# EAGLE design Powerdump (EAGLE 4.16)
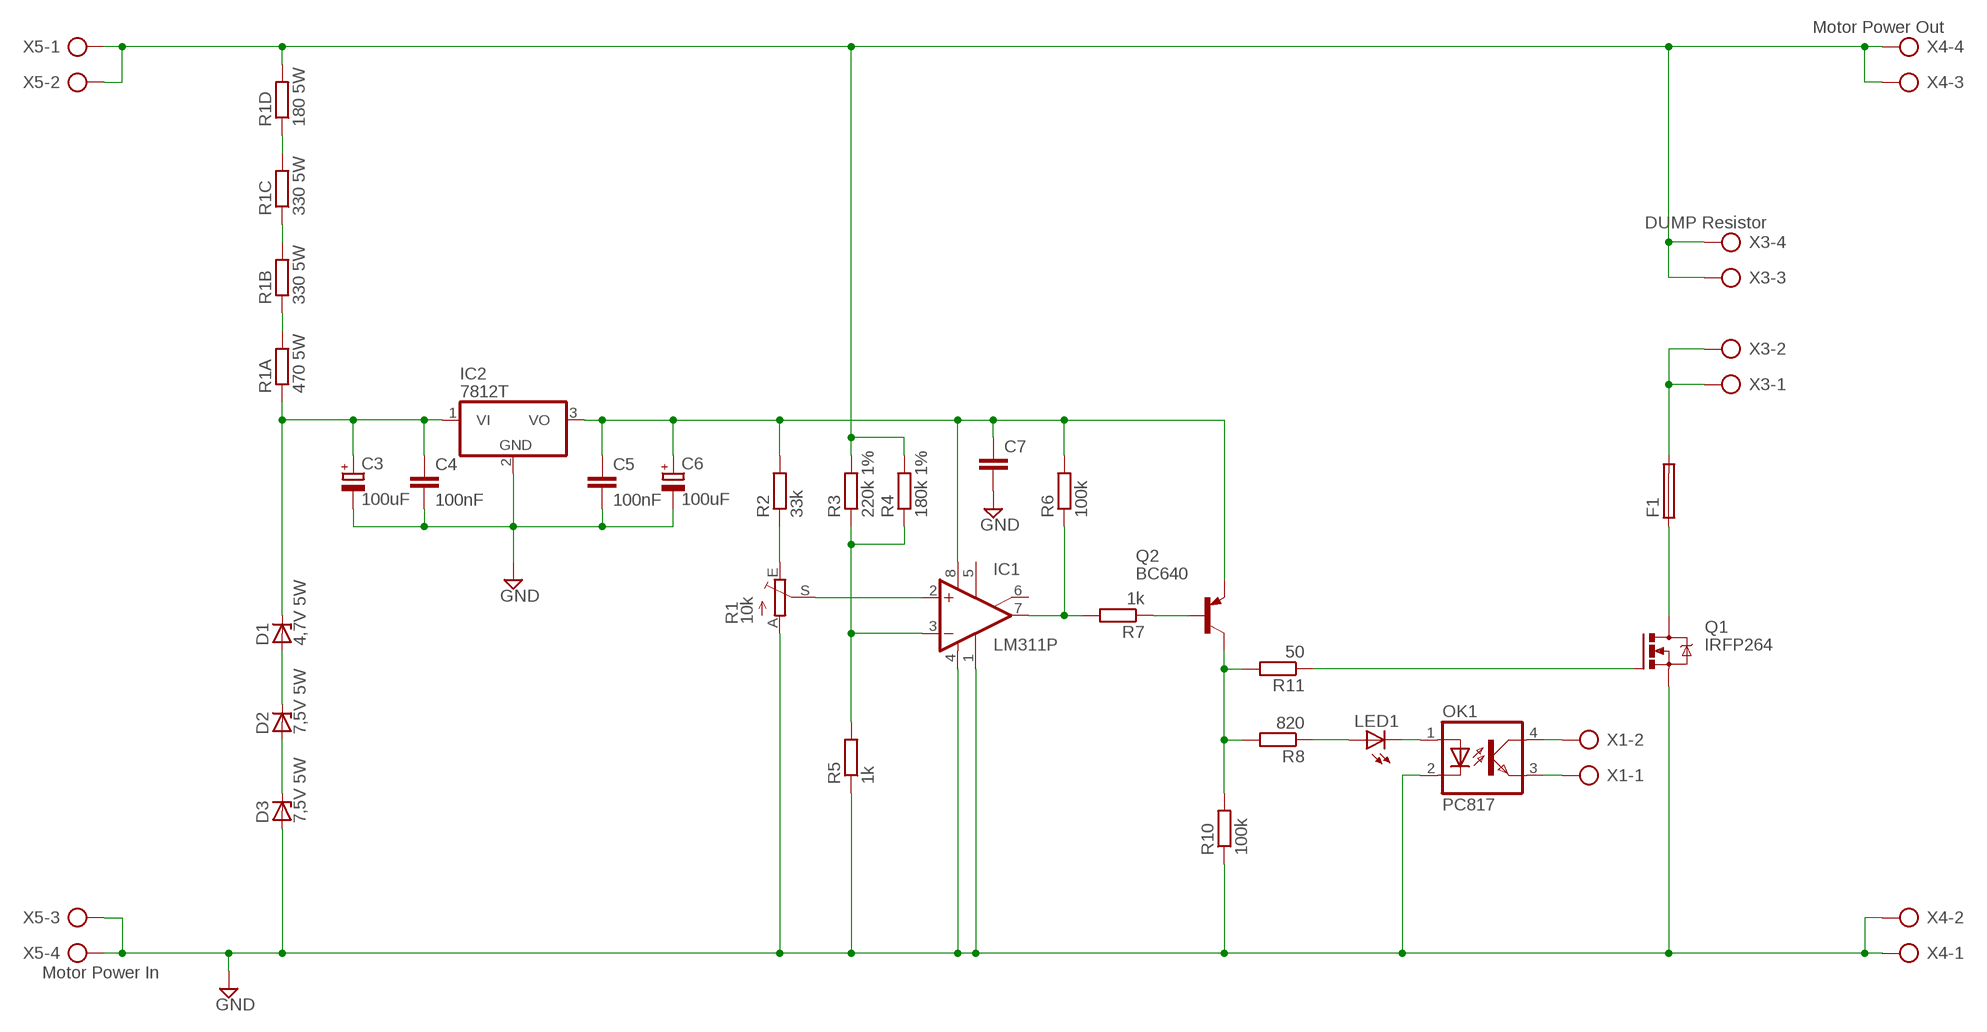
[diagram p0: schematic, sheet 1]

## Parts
C3  100uF  CPOL-EUE3.5-10  [E3,5-10]
C4  100nF  C-EU075-032X103  [C075-032X103]
C5  100nF  C-EU075-032X103  [C075-032X103]
C6  100uF  CPOL-EUE3.5-10  [E3,5-10]
C7  C-EU075-032X103  [C075-032X103]
D1  4,7V 5W  ZENER-DIODEC1702-15  [C1702-15]
D2  7,5V 5W  ZENER-DIODEC1702-15  [C1702-15]
D3  7,5V 5W  ZENER-DIODEC1702-15  [C1702-15]
F1  SH22,5A  [SH22,5A]
IC1  LM311P  LM311N  [DIL08]
IC2  7812T  [TO220H]
LED1  LED5MM  [LED5MM]
OK1  PC817  [DIL04]
Q1  IRFP264  IRFPC40  [TO247BV]
Q2  BC640  [TO92-BCE]
R1  10k  TRIM_EU-S64W  [S64W]
R1A  470 5W  R-EU_0922/22  [0922/22]
R1B  330 5W  R-EU_0922/22  [0922/22]
R1C  330 5W  R-EU_0922/22  [0922/22]
R1D  180 5W  R-EU_0922/22  [0922/22]
R2  33k  R-EU_0207/12  [0207/12]
R3  220k 1%  R-EU_0207/12  [0207/12]
R4  180k 1%  R-EU_0207/12  [0207/12]
R5  1k  R-EU_0207/12  [0207/12]
R6  100k  R-EU_0207/12  [0207/12]
R7  1k  R-EU_0207/12  [0207/12]
R8  820  R-EU_0207/12  [0207/12]
R10  100k  R-EU_0207/12  [0207/12]
R11  50  R-EU_0207/12  [0207/12]
X1  AK300/2  [AK300/2]
X3  DUMP Resistor  AK500/4  [AK500/4]
X4  Motor Power Out  AK500/4  [AK500/4]
X5  Motor Power In  AK500/4  [AK500/4]

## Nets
GND: C3.- C4.2 C5.2 C6.- C7.2 D3.A IC1.1(GND) IC1.4(V-) IC2.2(GND) OK1.2(C) Q1.S R1.A R5.1 R10.1 X4.1 X4.2 X5.3 X5.4
N$1: R1C.2 R1D.1
N$2: R1B.2 R1C.1
N$3: R1A.2 R1B.1
N$4: C3.+ C4.1 D1.C IC2.1(VI) R1A.1
N$6: C5.1 C6.+ C7.1 IC1.8(V+) IC2.3(VO) Q2.E R2.2 R6.2
N$7: IC1.7(OUT) R6.1 R7.2
N$8: Q2.B R7.1
N$11: IC1.3(-IN) R3.1 R4.1 R5.2
N$12: IC1.2(+IN) R1.S
N$13: R1.E R2.1
N$14: Q1.G R11.1
N$15: LED1.K(C) OK1.1(A)
N$16: LED1.A R8.1
N$17: Q2.C R8.2 R10.2 R11.2
N$18: R1D.2 R3.2 R4.2 X3.3 X3.4 X4.3 X4.4 X5.1 X5.2
N$19: F1.1 Q1.D
N$20: F1.2 X3.1 X3.2
N$21: D1.A D2.C
N$22: D2.A D3.C
N$24: OK1.3(EMIT) X1.1
N$25: OK1.4(COL) X1.2
Unconnected: IC1.5(ON) IC1.6(ON/STR)

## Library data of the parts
C3 C6 = rcl:CPOL-EU: POLARIZED CAPACITOR, European symbol
C4 C5 C7 = rcl:C-EU: CAPACITOR, European symbol
D1-D3 = diode:ZENER-DIODE: Z-Diode
F1 = fuse:SH22,5A: FUSE HOLDER
IC1 = linear:LM311: COMPARATOR
IC2 = linear:78*: Positive VOLTAGE REGULATOR Source: http://cache.national.com/ds/LM/LM78L05.pdf http://www.fairchildsemi.com/ds/LM/LM7805.pdf
LED1 = led:LED: LED
OK1 = optocoupler:PC817: SHARP OPTO COUPLER
Q1 = transistor-power:IRFPC40: N-CHANNEL MOS FET
Q2 = transistor-pnp:BC640*: PNP Transistror
R1 = pot:TRIM_EU-: POTENTIOMETER
R1A R1B R1C R1D R2-R8 R10 R11 = rcl:R-EU_: RESISTOR, European symbol
X1 = con-ptr500:AK300/2: CONNECTOR
X3-X5 = con-ptr500:AK500/4: CONNECTOR

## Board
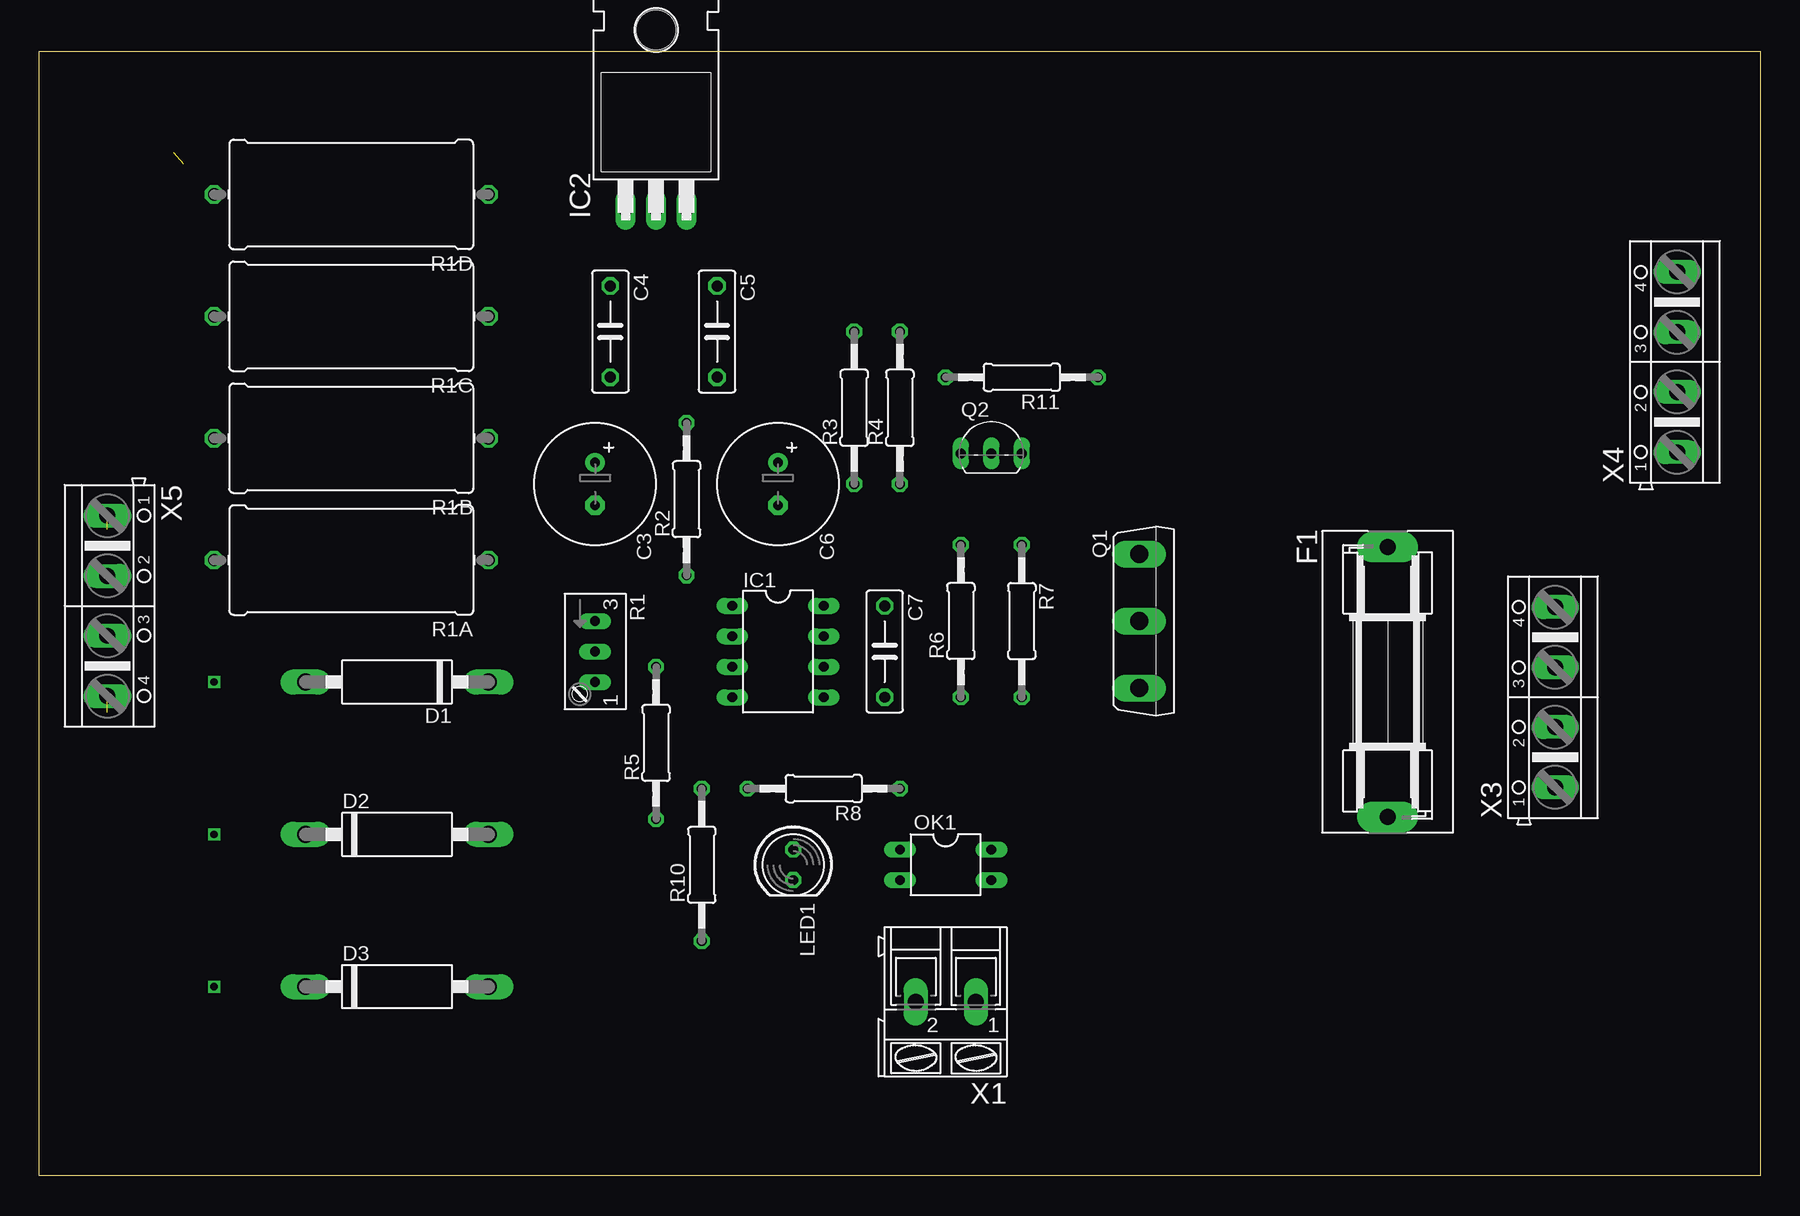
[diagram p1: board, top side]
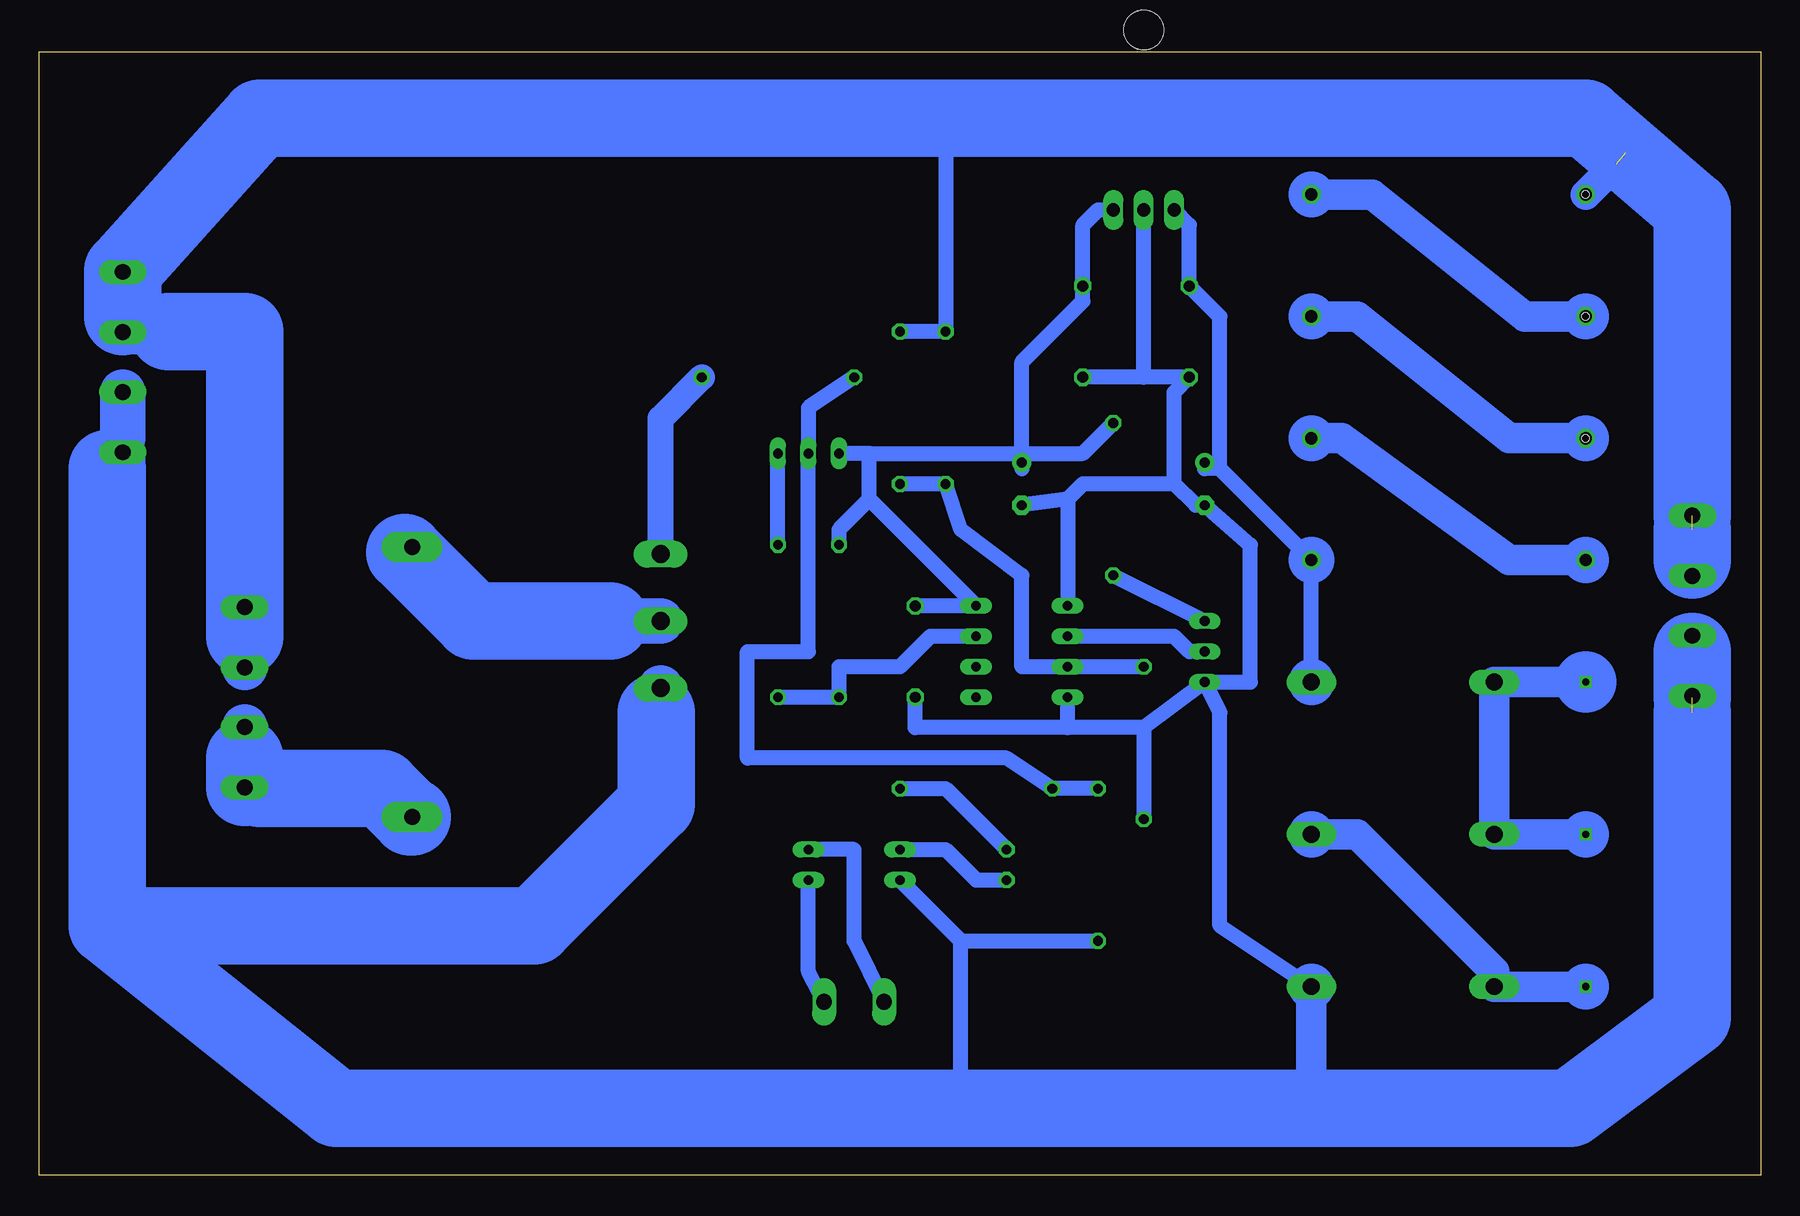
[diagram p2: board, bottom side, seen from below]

Size 143.49 x 93.65 mm. Coordinates in mm from the lower left corner, seen from the top.
Outline: 0,0 143.49,0 143.49,93.65 0,93.65 0,0
Copper layers (1*16): Top 0.035mm / dielectric 1.5mm / Bottom 0.035mm
Design rules "default": minimum track width 10mil, minimum drill 24mil, track to track 8mil, track to pad 8mil, pad to pad 8mil, via to via 8mil, smd to smd 8mil, copper to edge 40mil, drill to drill 8mil, minimum pad ring 10mil, minimum via ring 8mil, stop-mask expansion 4mil, vias tented up to drill 0mil, thermal gap 10mil
Holes 0.6 mm at 14.6,81.75 14.6,71.59 14.6,61.43

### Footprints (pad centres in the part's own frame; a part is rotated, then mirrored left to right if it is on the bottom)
E3,5-10 = drill 0.813 pad 1.6 round: + -1.778,0 | drill 0.813 pad 1.6 octagon: - 1.778,0
C075-032X103 = drill 0.914 octagon: 1 -3.81,0; 2 3.81,0
C1702-15 = drill 1.397 long: A 7.62,0; C -7.62,0
SH22,5A = drill 1.321 pad 2.54 long: 1 -11.252,0; 2 11.252,0
DIL08 = drill 0.813 long: 1 -3.81,-3.81; 2 -1.27,-3.81; 3 1.27,-3.81; 4 3.81,-3.81; 5 3.81,3.81; 6 1.27,3.81; 7 -1.27,3.81; 8 -3.81,3.81
TO220H = drill 1.118 long: 1 -2.54,-10.16; 2 0,-10.16; 3 2.54,-10.16 | hole 3.302: 0,4.826
LED5MM = drill 0.813 octagon: A -1.27,0; K 1.27,0
DIL04 = drill 0.813 long: 1 -1.27,-3.81; 2 1.27,-3.81; 3 1.27,3.81; 4 -1.27,3.81
TO247BV = drill 1.499 long: D 0,-2.921; G -5.588,-2.921; S 5.588,-2.921
TO92-BCE = drill 0.813 long: B 2.54,0; C 0,0; E -2.54,0
S64W = drill 0.813 long: A 2.54,1.27; E -2.54,1.27; S 0,1.27
0922/22 = drill 1.016 octagon: 1 -11.43,0; 2 11.43,0
0207/12 = drill 0.813 octagon: 1 -6.35,0; 2 6.35,0
AK300/2 = drill 1.321 long: 1 -2.515,0; 2 2.489,0
AK500/4 = drill 1.321 long: 1 -7.518,0; 2 -2.489,0; 3 2.489,0; 4 7.518,0

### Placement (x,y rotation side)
C3  46.35,57.62 270 top
C4  47.62,70.32 270 top
C5  56.51,70.32 270 top
C6  61.59,57.62 270 top
C7  70.48,43.65 270 top
D1  29.84,41.11 180 top
D2  29.84,28.41 0 top
D3  29.84,15.71 0 top
F1  112.39,41.11 270 top
IC1  61.59,43.65 270 top
IC2  51.43,90.64 0 top
LED1  62.86,25.87 270 top
OK1  75.56,25.87 270 top
Q1  94.61,46.19 270 top
Q2  79.37,60.16 0 top
R1  45.08,43.65 270 top
R1A  26.03,51.27 180 top
R1B  26.03,61.43 180 top
R1C  26.03,71.59 180 top
R1D  26.03,81.75 180 top
R2  53.97,56.35 90 top
R3  67.94,63.97 90 top
R4  71.75,63.97 90 top
R5  51.43,36.03 90 top
R6  76.83,46.19 90 top
R7  81.91,46.19 270 top
R8  65.4,32.22 180 top
R10  55.24,25.87 90 top
R11  81.91,66.51 180 top
X1  75.56,14.44 180 top
X3  126.36,39.84 90 top
X4  136.52,67.78 90 top
X5  5.71,47.46 270 top

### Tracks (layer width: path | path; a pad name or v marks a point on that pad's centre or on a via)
GND  (1 unrouted)
  Bottom 0.254: 5.71,43.65 X5.3 | X4.1 136.52,61.43
  Bottom 1.27: 48.89,57.62 47.11,55.84 C3.- 42.54,52.54 42.54,41.11 R1.A | 48.89,57.62 48.89,65.24 C4.2 51.43,66.51 | 51.43,66.51 C5.2 | 51.43,66.51 IC2.2 | 48.89,57.62 56.51,57.62 57.78,56.35 | 57.78,56.35 C6.- | R1.A 51.43,37.3 | 51.43,37.3 57.78,37.3 | 57.78,37.3 70.48,37.3 C7.2 | 57.78,37.3 IC1.4 | R1.A 45.08,38.57 45.08,20.79 D3.A | 66.67,5.55 66.67,19.52 | 66.67,19.52 OK1.2 | 51.43,37.3 R5.1 | 66.67,19.52 R10.1 | 57.78,56.35 IC1.1
  Bottom 2.54: 37.46,5.55 D3.A
  Bottom 3.81: 5.71,42.38 X5.3 | 137.79,58.89 136.52,58.89 X4.1 | 136.52,61.43 X4.2 | Q1.S 91.69,38.95 92.07,38.57
  Bottom 6.452: 5.71,39.84 X5.4 5.71,42.38 5.71,43.65 | 137.79,20.79 137.79,58.89 | 92.07,38.57 92.07,30.95 102.23,20.79 137.79,20.79 | 137.79,20.79 118.74,5.55 66.67,5.55 37.46,5.55 15.87,5.55 5.71,13.17 5.71,38.57
N$1
  Bottom 2.54: R1C.2 19.68,71.59 32.38,81.75 R1D.1
N$2
  Bottom 2.54: R1B.2 20.95,61.43 33.65,71.59 R1C.1
N$3
  Bottom 2.54: R1B.1 34.92,61.43 20.95,51.27 R1A.2
N$4
  Bottom 1.27: 45.08,58.89 R1A.1 D1.C | C3.+ 46.35,58.89 45.08,58.89 | IC2.1 47.62,79.21 C4.1 45.08,71.59 45.08,58.89
N$6
  Bottom 0.254: 61.59,60.16 62.86,60.16
  Bottom 1.27: C7.1 IC1.8 74.29,56.35 | IC2.3 55.24,80.48 56.51,79.21 C5.1 56.51,72.86 61.59,67.78 61.59,60.16 | 74.29,56.35 74.29,60.16 | 74.29,60.16 61.59,60.16 | 61.59,58.89 C6.+ 61.59,60.16 | R2.2 56.51,60.16 61.59,60.16 | 74.29,60.16 Q2.E | R6.2 76.83,53.81 74.29,56.35
N$7
  Bottom 1.27: R7.2 R6.1 76.83,42.38 71.75,42.38 69.21,44.92 IC1.7
N$8
  Bottom 1.27: R7.1 Q2.B
N$11
  Bottom 1.27: R4.1 R3.1 66.67,53.81 61.59,50 61.59,42.38 IC1.3 R5.2
N$12
  Bottom 1.27: R1.S 47.62,43.65 48.89,44.92 IC1.2
N$13
  Bottom 1.27: R1.E R2.1
N$14
  Bottom 2.184: Q1.G 91.69,63.08 R11.1
N$15
  Bottom 1.27: OK1.1 67.94,27.14 65.4,24.6 LED1.K
N$16
  Bottom 1.27: R8.1 67.94,32.22 LED1.A
N$17
  Bottom 1.27: R10.2 R8.2 62.86,34.76 84.45,34.76 84.45,43.65 79.37,43.65 Q2.C 79.37,63.97 R11.2
N$18  (2 unrouted)
  Bottom 0.254: 136.52,71.59 136.52,70.32
  Bottom 1.27: R4.2 R3.2 67.94,88.1
  Bottom 2.54: R1D.2 12.06,84.29
  Bottom 3.81: X5.1 5.71,55.08 | 136.52,75.4 X4.4 | X3.4 126.36,47.46 | X4.3 136.52,70.32 132.71,70.32 | 126.36,44.92 X3.3 | X5.2 5.71,51.27
  Bottom 6.452: X4.4 136.52,71.59 | X5.1 5.71,80.48 14.6,88.1 67.94,88.1 125.09,88.1 136.52,75.4 | 132.71,70.32 126.36,70.32 X3.4 126.36,44.92 | 5.71,51.27 5.71,53.81
N$19
  Bottom 0.254: F1.1 112.39,52.54 113.02,51.9
  Bottom 3.81: 113.02,51.9 113.66,52.54 | Q1.D 95.88,46.19
  Bottom 6.452: 113.02,51.9 107.31,46.19 95.88,46.19
N$20
  Bottom 3.81: 126.36,32.22 X3.1 122.65,32.32 122.55,32.22 | 126.36,34.76 X3.2
  Bottom 6.452: F1.2 112.57,29.86 114.93,32.22 122.55,32.22 125.09,32.22 | X3.1 126.36,34.76
N$21  (via drill 0.6)
  Bottom 2.54: v14.6,41.11 D1.A D2.C v14.6,28.41
N$22  (via drill 0.6)
  Bottom 2.54: v14.6,15.71 D3.C 22.22,16.98 33.65,28.41 D2.A
N$24
  Bottom 1.27: OK1.3 79.37,16.98 X1.1
N$25
  Bottom 1.27: OK1.4 75.56,27.14 75.56,19.52 X1.2
(copper drawn outside any net)
  shapes: Bottom circle x13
